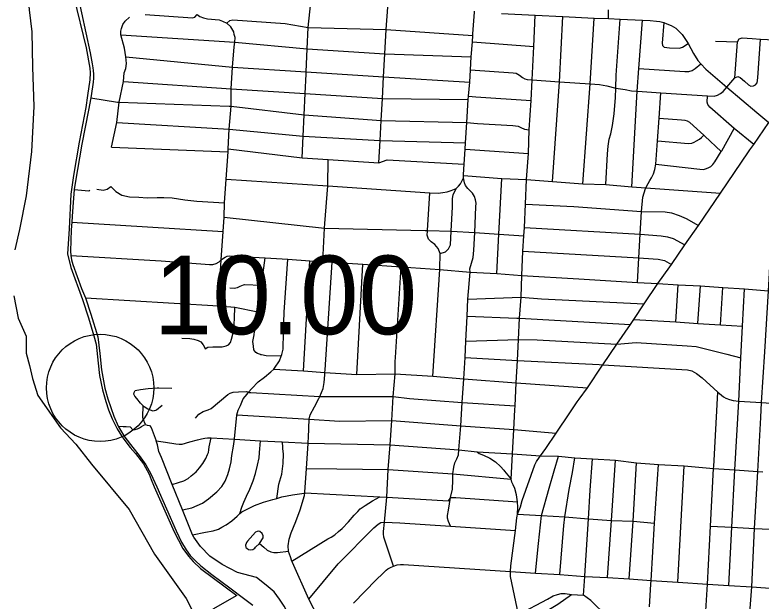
# Model space of a CAD drawing. Extents: x 1729596 to 1934326, y 644115 to 911751.
# Drawn here: x 1801847 to 1812277, y 731420 to 739620 of the extents above; entities that cross this region are included whole.
import ezdxf

# ---------------------------------------------------------------- set-up
doc = ezdxf.new("R2010")
doc.units = 0
for name, color, linetype in [('Default', 7, 'Continuous'), ('GM_X_City_Street', 7, 'Continuous'), ('GM_X_Corporation', 7, 'Continuous'), ('GM_X_Township', 7, 'Continuous'), ('GM_X_US_Route', 7, 'Continuous')]:
    doc.layers.add(name, color=color, linetype=linetype)

msp = doc.modelspace()

# ---------------------------------------------------------------- linework, layer by layer
at = {"layer": 'Default'}
msp.add_circle((1803038, 734403), 750, dxfattribs=at)
at = {"layer": 'GM_X_City_Street'}
for points in [[(1805917, 738818), (1805917, 738825), (1805932, 739144), (1805946, 739442), (1805982, 739794)], [(1806936, 737550), (1806953, 737863), (1806968, 738144), (1806985, 738451), (1807001, 738756), (1807018, 739077), (1807035, 739414), (1807059, 739728)], [(1810142, 739569), (1810142, 739692)], [(1803196, 737770), (1803273, 738114), (1803303, 738398), (1803363, 738691), (1803373, 738808), (1803396, 738870), (1803405, 738941), (1803398, 739035), (1803381, 739154), (1803329, 739340), (1803329, 739395), (1803335, 739430), (1803354, 739485), (1803387, 739533), (1803448, 739591)], [(1803669, 739626), (1804328, 739580), (1804361, 739591), (1804394, 739625), (1804434, 739597), (1804481, 739578), (1804540, 739566), (1804701, 739552), (1804751, 739534), (1804809, 739505), (1804849, 739541), (1804892, 739552), (1805623, 739499), (1805946, 739442), (1807035, 739414), (1808248, 739330)], [(1808250, 739355), (1808272, 739661), (1808272, 739674)], [(1808647, 739638), (1809119, 739616), (1809505, 739596), (1809946, 739574), (1810142, 739569), (1810308, 739562), (1810618, 739545), (1810728, 739540), (1810813, 739533), (1810862, 739527), (1810916, 739514), (1810962, 739497), (1811018, 739471), (1811084, 739433), (1811138, 739385), (1811174, 739345), (1811257, 739222), (1811333, 739081), (1811395, 738983), (1811435, 738935), (1811507, 738862), (1811798, 738609), (1812216, 738255), (1812384, 738116)], [(1808836, 734094), (1808839, 734150), (1808853, 734473), (1808872, 734786), (1808886, 735079), (1808902, 735376), (1808922, 735673), (1808931, 735977), (1808949, 736314), (1808962, 736531), (1808969, 736648), (1808986, 736972), (1808999, 737316), (1809026, 737680), (1809037, 738014), (1809064, 738421), (1809077, 738710), (1809099, 739180), (1809119, 739616)], [(1809360, 737289), (1809461, 738686), (1809505, 739596)], [(1804914, 739175), (1804920, 739241), (1804927, 739306), (1804914, 739346), (1804905, 739384), (1804864, 739452), (1804809, 739505)], [(1809787, 737259), (1809888, 738656), (1809946, 739574)], [(1810107, 737246), (1810128, 737678), (1810139, 737783), (1810153, 737881), (1810175, 737958), (1810200, 738074), (1810222, 738237), (1810240, 738467), (1810248, 738597), (1810252, 738778), (1810308, 739562)], [(1810471, 737213), (1810547, 738553), (1810569, 738870), (1810618, 739545)], [(1810916, 739514), (1810894, 739226), (1810898, 739193), (1810923, 739170), (1810999, 739161), (1811136, 739155), (1811178, 739168), (1811257, 739222)], [(1803329, 739340), (1804920, 739241), (1805932, 739144), (1807018, 739077), (1808225, 739036)], [(1808119, 737386), (1808128, 737531), (1808143, 737743), (1808144, 737832), (1808166, 738116), (1808185, 738436), (1808188, 738483), (1808207, 738680), (1808215, 738854), (1808225, 739036), (1808243, 739244), (1808248, 739330), (1808250, 739355)], [(1811639, 739254), (1811948, 739245), (1811973, 739285), (1812011, 739300), (1812154, 739292), (1812270, 739283), (1812465, 739271), (1812521, 739249), (1812562, 739224), (1812675, 739086)], [(1811910, 738741), (1811952, 738759), (1811986, 738747), (1812047, 738692), (1812102, 738644), (1812136, 738625), (1812172, 738627), (1812201, 738642), (1812223, 738671), (1812230, 738739), (1812270, 739283)], [(1804691, 735551), (1804731, 736194), (1804757, 736590), (1804770, 736789), (1804778, 736991), (1804798, 737324), (1804828, 737705), (1804828, 737745), (1804844, 738022), (1804868, 738342), (1804870, 738588), (1804889, 738889), (1804914, 739175)], [(1808243, 739244), (1809099, 739180)], [(1811798, 738609), (1811910, 738741), (1811948, 739245)], [(1803398, 739035), (1804889, 738889), (1805917, 738825), (1807001, 738756), (1808207, 738680)], [(1810569, 738870), (1811209, 738830), (1811265, 738828), (1811315, 738844), (1811357, 738870), (1811435, 738935)], [(1805861, 737623), (1805875, 737923), (1805889, 738223), (1805903, 738522), (1805916, 738792), (1805917, 738818)], [(1808215, 738854), (1808812, 738810), (1808853, 738805), (1808901, 738777), (1808944, 738745), (1808973, 738728), (1809006, 738717), (1809077, 738710), (1809461, 738686), (1809888, 738656), (1810017, 738645), (1810120, 738630), (1810248, 738597), (1810378, 738576), (1810466, 738557), (1810547, 738553), (1810551, 738553)], [(1803363, 738691), (1804870, 738588), (1805903, 738522), (1806985, 738451), (1808185, 738436)], [(1810551, 738553), (1810876, 738530), (1811529, 738486), (1811623, 738485), (1811668, 738497), (1811708, 738519), (1811747, 738548), (1811798, 738609)], [(1802908, 738458), (1803281, 738402)], [(1808188, 738483), (1808288, 738476), (1809064, 738421)], [(1810661, 737192), (1810665, 737203), (1810698, 737261), (1810724, 737305), (1810747, 737341), (1810771, 737397), (1810790, 737458), (1810807, 737532), (1810829, 737857), (1810853, 738175), (1810876, 738530)], [(1812174, 737806), (1811903, 738031), (1811561, 738329), (1811534, 738365), (1811525, 738401), (1811529, 738486)], [(1803281, 738402), (1803303, 738398), (1804840, 738343)], [(1804840, 738343), (1804868, 738342), (1805889, 738223), (1806968, 738144), (1808166, 738116)], [(1810853, 738175), (1811164, 738153), (1811212, 738149), (1811246, 738140), (1811276, 738118), (1811334, 738068), (1811476, 737940), (1811491, 737926), (1811720, 737709)], [(1803273, 738114), (1804844, 738022), (1805875, 737923), (1806953, 737863), (1806959, 737863), (1808144, 737832)], [(1808166, 738116), (1808315, 738102), (1808805, 738072), (1808881, 738064), (1808919, 738045), (1808969, 738020), (1809037, 738014)], [(1810807, 737532), (1811421, 737461), (1811473, 737459), (1811502, 737466), (1811538, 737482), (1811574, 737502), (1811602, 737527), (1811629, 737567), (1811720, 737709), (1811727, 737720), (1811903, 738031)], [(1812120, 737732), (1812174, 737806), (1812384, 738116), (1812387, 738121)], [(1810829, 737857), (1811263, 737821), (1811311, 737828), (1811341, 737840), (1811376, 737859), (1811416, 737883), (1811442, 737907), (1811476, 737940)], [(1812121, 731255), (1812147, 731618), (1812186, 732437), (1812230, 733234), (1812272, 733988), (1812285, 734197), (1812328, 734907), (1812381, 735762), (1812390, 735924), (1812420, 736462), (1812451, 736956), (1812476, 737414), (1812477, 737457), (1812474, 737530), (1812463, 737630), (1812435, 737794), (1812425, 737857)], [(1803196, 737770), (1804828, 737705)], [(1804828, 737745), (1805861, 737623), (1806227, 737598), (1806936, 737550), (1807052, 737595), (1808128, 737531)], [(1808143, 737743), (1809026, 737680)], [(1811709, 737125), (1812102, 737707), (1812120, 737732)], [(1806180, 736700), (1806221, 737230), (1806227, 737598)], [(1804798, 737324), (1806221, 737230)], [(1806221, 737230), (1807649, 737132), (1807762, 737128), (1807830, 737135), (1807891, 737145), (1807944, 737162), (1808013, 737193), (1808047, 737223), (1808075, 737255), (1808117, 737339)], [(1807938, 732467), (1807908, 732535), (1807893, 732581), (1807895, 732619), (1807906, 732691), (1807937, 732869), (1807962, 732986), (1807967, 733114), (1807970, 733200), (1807981, 733295), (1807995, 733354), (1808026, 733412), (1808048, 733465), (1808051, 733537), (1808081, 733874), (1808098, 734200), (1808123, 734531), (1808141, 734826), (1808150, 735056), (1808171, 735406), (1808179, 735645), (1808209, 736022), (1808208, 736066), (1808251, 736228), (1808261, 736331), (1808278, 736575), (1808292, 736936), (1808296, 736989), (1808286, 737032), (1808271, 737080), (1808243, 737125), (1808180, 737191), (1808145, 737235), (1808130, 737272), (1808117, 737339), (1808118, 737375), (1808119, 737386)], [(1808118, 737375), (1808655, 737333), (1808999, 737316), (1809360, 737289), (1809787, 737259), (1810107, 737246), (1810471, 737213), (1810665, 737203), (1811709, 737125)], [(1808584, 736001), (1808612, 736555), (1808655, 737333)], [(1802990, 737183), (1803079, 737170), (1803137, 737183), (1803190, 737220)], [(1803190, 737220), (1803257, 737149), (1803343, 737097), (1803448, 737075), (1803580, 737069), (1803697, 737060), (1803835, 737066), (1803927, 737066), (1804047, 737060), (1804223, 737032), (1804389, 737014), (1804778, 736991)], [(1807791, 736284), (1807864, 736308), (1807907, 736348), (1807937, 736405), (1807947, 736595), (1807962, 736937), (1807966, 737052), (1807975, 737103), (1808013, 737193)], [(1810548, 735879), (1810570, 736221), (1810587, 736552), (1810606, 736869), (1810624, 737073), (1810661, 737192)], [(1802677, 737178), (1802879, 737161), (1802896, 737168)], [(1807613, 736595), (1807614, 736605), (1807649, 737132)], [(1811001, 736096), (1811024, 736129), (1811213, 736402), (1811402, 736672), (1811709, 737125)], [(1808986, 736972), (1809660, 736939), (1810606, 736869), (1810935, 736864), (1811024, 736853), (1811132, 736816), (1811230, 736772), (1811402, 736672)], [(1804770, 736789), (1806175, 736638), (1807581, 736606)], [(1802642, 736721), (1804757, 736590)], [(1806150, 736172), (1806175, 736638), (1806180, 736700)], [(1807581, 736606), (1807614, 736605), (1807947, 736595), (1808278, 736575), (1808612, 736555), (1808962, 736531)], [(1807791, 736284), (1807791, 736284), (1807764, 736351), (1807717, 736408), (1807667, 736448), (1807630, 736485), (1807610, 736541), (1807613, 736595)], [(1808969, 736648), (1810587, 736552), (1810882, 736532), (1810971, 736516), (1811049, 736494), (1811213, 736402)], [(1802630, 736256), (1803891, 736178), (1804565, 736128), (1804614, 736130), (1804662, 736143), (1804700, 736164), (1804731, 736194), (1804762, 736218), (1804785, 736232), (1804816, 736244), (1804847, 736250), (1805345, 736222), (1805662, 736202), (1805971, 736182), (1806150, 736172), (1806280, 736163), (1806708, 736134), (1807247, 736097), (1807787, 736060), (1808209, 736022), (1808584, 736001), (1808931, 735977), (1809731, 735930), (1810548, 735879), (1810835, 735862), (1811120, 735845), (1811430, 735829), (1811741, 735808), (1812043, 735789), (1812381, 735762)], [(1807787, 736069), (1807791, 736284)], [(1808949, 736314), (1810570, 736221), (1810768, 736207), (1810840, 736204), (1810926, 736187), (1811024, 736129)], [(1804188, 732696), (1804318, 732724), (1804467, 732790), (1804554, 732851), (1804671, 732949), (1804738, 733021), (1804785, 733096), (1804824, 733191), (1804847, 733269), (1804872, 733367), (1804881, 733458), (1804904, 733588), (1804917, 733684), (1804918, 733692), (1804942, 733927), (1804947, 734015), (1804950, 734027), (1804966, 734093), (1805001, 734154), (1805036, 734250), (1805093, 734317), (1805114, 734341), (1805160, 734394), (1805247, 734487), (1805334, 734554), (1805425, 734629), (1805464, 734666), (1805476, 734678), (1805545, 734779), (1805569, 734845), (1805578, 734869), (1805597, 734945), (1805603, 735178), (1805612, 735464), (1805662, 736202)], [(1805285, 734867), (1805279, 734868), (1805239, 734883), (1805215, 734899), (1805188, 734933), (1805180, 734985), (1805175, 735053), (1805190, 735143), (1805197, 735193), (1805202, 735205), (1805219, 735248), (1805228, 735312), (1805239, 735402), (1805243, 735468), (1805246, 735528), (1805257, 735575), (1805273, 735611), (1805282, 735657), (1805291, 735783), (1805295, 735841), (1805345, 736222)], [(1805880, 734639), (1805971, 736182)], [(1806182, 734654), (1806280, 736163)], [(1806625, 734590), (1806708, 736134)], [(1807167, 734828), (1807247, 736097)], [(1807689, 734567), (1807787, 736060), (1807787, 736069)], [(1810060, 734721), (1810063, 734726), (1810261, 735013), (1810450, 735291), (1810500, 735361), (1810645, 735578), (1810835, 735862), (1811001, 736096)], [(1804851, 735800), (1804913, 735799), (1804959, 735809), (1804995, 735824), (1805041, 735844), (1805044, 735846)], [(1805044, 735846), (1805044, 735846), (1805056, 735851), (1805295, 735841)], [(1811087, 735329), (1811120, 735845)], [(1811395, 735302), (1811430, 735829)], [(1811709, 735285), (1811741, 735808)], [(1811826, 731636), (1811868, 732452), (1811911, 733255), (1811966, 734219), (1811995, 734825), (1812016, 735265), (1812043, 735789)], [(1802832, 735664), (1804691, 735551), (1804923, 735530), (1805243, 735468)], [(1808179, 735645), (1808922, 735673), (1809206, 735650), (1810645, 735578)], [(1804908, 735216), (1804911, 735292), (1804916, 735376), (1804923, 735530)], [(1808171, 735406), (1808861, 735378)], [(1808861, 735378), (1808902, 735376), (1810450, 735291)], [(1810500, 735361), (1811087, 735329), (1811395, 735302), (1811709, 735285), (1812016, 735265)], [(1804614, 734975), (1804615, 734975), (1804669, 734977), (1804743, 734978), (1804800, 734989), (1804832, 735005), (1804860, 735037), (1804873, 735082), (1804892, 735152), (1804908, 735216)], [(1804908, 735216), (1805202, 735205)], [(1804182, 735098), (1804292, 735093), (1804350, 735082), (1804410, 735064), (1804448, 735045), (1804479, 735005), (1804501, 734963), (1804505, 734949), (1804545, 734970), (1804614, 734975)], [(1808150, 735056), (1808886, 735079), (1809148, 735074), (1810261, 735013), (1810531, 735037), (1811244, 734990), (1811368, 734981), (1811798, 734873), (1811995, 734825)], [(1805569, 734845), (1805361, 734853), (1805295, 734865), (1805285, 734867)], [(1807139, 731910), (1807031, 732230), (1807006, 732314), (1806998, 732361), (1807001, 732395), (1807011, 732524), (1807044, 732873), (1807065, 733262), (1807091, 733604), (1807116, 733946), (1807135, 734281), (1807160, 734601), (1807163, 734774), (1807167, 734828)], [(1808141, 734826), (1808872, 734786), (1810014, 734728)], [(1809707, 734206), (1809732, 734244), (1809849, 734403), (1810060, 734721)], [(1810014, 734728), (1810063, 734726), (1811249, 734653), (1811309, 734640), (1811375, 734603), (1811455, 734541), (1811674, 734342), (1811722, 734299), (1811752, 734278), (1811786, 734258), (1811837, 734238), (1811885, 734227), (1811966, 734219), (1812285, 734197), (1812611, 734176), (1812908, 734157), (1813305, 734127), (1813550, 734107), (1813957, 734080), (1814298, 734057), (1814552, 734038), (1814840, 734018), (1815014, 734009), (1815058, 734013)], [(1805464, 734666), (1805880, 734639), (1806180, 734620), (1806625, 734590), (1807160, 734601), (1807689, 734567), (1808123, 734531), (1808853, 734473), (1809849, 734403)], [(1805950, 733709), (1805958, 733964), (1805973, 734026), (1806033, 734137), (1806094, 734254), (1806107, 734284), (1806154, 734395), (1806171, 734477), (1806178, 734585), (1806180, 734620), (1806182, 734654)], [(1803905, 734156), (1803826, 734091), (1803778, 734076), (1803704, 734107), (1803656, 734137), (1803641, 734152), (1803603, 734188), (1803549, 734252), (1803523, 734286), (1803508, 734313), (1803512, 734338), (1803530, 734364), (1803601, 734379), (1803709, 734394), (1803834, 734402)], [(1803834, 734402), (1803834, 734402), (1803861, 734403), (1804042, 734399)], [(1804372, 733979), (1804418, 734035), (1804479, 734074), (1804549, 734097), (1804588, 734115), (1804822, 734308), (1804858, 734328), (1804897, 734345), (1804971, 734348), (1805085, 734351), (1805114, 734341), (1805123, 734337), (1805144, 734336), (1805144, 734336)], [(1805144, 734336), (1806107, 734284), (1806110, 734284), (1807135, 734281), (1807363, 734253), (1808098, 734200), (1808839, 734150)], [(1811615, 733301), (1811674, 734342)], [(1809179, 733432), (1809194, 733454), (1809267, 733557), (1809412, 733768), (1809604, 734052), (1809707, 734206)], [(1803673, 733889), (1803638, 733964), (1803635, 733998), (1803641, 734152)], [(1808810, 733047), (1808794, 733084), (1808782, 733125), (1808804, 733479), (1808822, 733821), (1808836, 734094)], [(1804950, 734027), (1805958, 733964), (1806384, 733939), (1806384, 733939)], [(1803288, 733867), (1803360, 733863), (1803404, 733861), (1803459, 733860), (1803494, 733817), (1803528, 733821), (1803561, 733829), (1803587, 733846), (1803617, 733864), (1803649, 733882), (1803673, 733889), (1803695, 733883), (1803727, 733875), (1803751, 733850), (1803778, 733776), (1803823, 733664), (1803951, 733641), (1804095, 733621), (1804141, 733616), (1804187, 733614), (1804294, 733647), (1804398, 733674), (1804455, 733689), (1804503, 733700), (1804537, 733706), (1804583, 733703), (1804589, 733702), (1804917, 733684), (1805278, 733664), (1805582, 733648), (1805943, 733628), (1805947, 733627), (1807091, 733604), (1808051, 733537), (1808310, 733509), (1808338, 733486), (1808395, 733462), (1808484, 733420), (1808564, 733369), (1808634, 733305), (1808683, 733250)], [(1806384, 733939), (1807116, 733946), (1808081, 733874), (1808822, 733821), (1809412, 733768)], [(1806089, 731187), (1805983, 731144), (1805894, 731117), (1805818, 731106), (1805752, 731116), (1805706, 731162), (1805682, 731213), (1805613, 731348), (1805545, 731445), (1805470, 731548), (1805360, 731645), (1805225, 731749), (1804957, 731818), (1804744, 731930), (1804573, 732048), (1804440, 732185), (1804347, 732312), (1804331, 732348), (1804188, 732696), (1804046, 733050), (1803895, 733427), (1803860, 733514), (1803839, 733606), (1803823, 733664)], [(1804046, 733050), (1804133, 733077), (1804210, 733104), (1804270, 733134), (1804313, 733171), (1804379, 733226), (1804428, 733282), (1804475, 733345), (1804514, 733413), (1804540, 733470), (1804551, 733500), (1804559, 733536), (1804564, 733580), (1804589, 733702)], [(1805267, 733496), (1805267, 733497), (1805271, 733552), (1805278, 733664)], [(1805508, 732857), (1805538, 733054), (1805577, 733195), (1805597, 733343), (1805601, 733482), (1805593, 733552), (1805594, 733596), (1805582, 733648)], [(1806181, 730993), (1806089, 731187), (1805956, 731446), (1805726, 731959), (1805719, 731978), (1805699, 732037), (1805670, 732113), (1805670, 732117), (1805665, 732193), (1805680, 732287), (1805707, 732373), (1805773, 732532), (1805833, 732699), (1805895, 732898), (1805900, 732934), (1805901, 732942), (1805923, 733275), (1805947, 733624), (1805947, 733627), (1805948, 733644), (1805950, 733709)], [(1804991, 732646), (1805021, 732734), (1805048, 732805), (1805085, 732889), (1805132, 732988), (1805176, 733104), (1805211, 733207), (1805240, 733323), (1805261, 733426), (1805267, 733496)], [(1808310, 733509), (1808804, 733479), (1809194, 733454), (1809444, 733447), (1809676, 733426), (1809921, 733412), (1810242, 733390), (1810534, 733355), (1810842, 733332), (1811200, 733312), (1811614, 733277), (1811911, 733255), (1812230, 733234), (1812301, 733229)], [(1808869, 732608), (1808873, 732635), (1808914, 732738), (1808936, 732826), (1809113, 733327), (1809139, 733374), (1809179, 733432)], [(1809123, 731812), (1809166, 732227), (1809210, 732616), (1809316, 732999), (1809387, 733244), (1809444, 733447)], [(1809463, 731792), (1809521, 732477), (1809533, 732598), (1809596, 732979), (1809639, 733220), (1809676, 733426)], [(1809814, 731773), (1809867, 732572), (1809887, 732972), (1809921, 733412)], [(1810132, 731748), (1810188, 732549), (1810242, 733390)], [(1810433, 731730), (1810491, 732538), (1810534, 733355)], [(1810737, 731659), (1810740, 731707), (1810786, 732511), (1810842, 733332)], [(1805923, 733275), (1806348, 733270)], [(1806348, 733270), (1807065, 733262), (1807970, 733200), (1808782, 733125)], [(1808683, 733250), (1808692, 733239), (1808782, 733125)], [(1811112, 731685), (1811200, 733312)], [(1812065, 729436), (1811901, 729654), (1811708, 729901), (1811521, 730157), (1811483, 730224), (1811456, 730293), (1811450, 730348), (1811448, 730407), (1811451, 730493), (1811464, 730634), (1811478, 730967), (1811504, 731286), (1811526, 731655), (1811571, 732470), (1811614, 733277), (1811615, 733301)], [(1808873, 732635), (1808878, 732734), (1808872, 732807), (1808857, 732908), (1808833, 732997), (1808810, 733047)], [(1804331, 732348), (1804510, 732382), (1804617, 732405), (1804695, 732428), (1804738, 732453), (1804800, 732487), (1804877, 732542), (1804952, 732609), (1804991, 732646), (1805017, 732670), (1805194, 732756), (1805321, 732806), (1805451, 732841), (1805508, 732857), (1805578, 732877), (1805727, 732906), (1805888, 732932)], [(1805888, 732932), (1805900, 732934), (1806946, 732878), (1807044, 732873), (1807045, 732873), (1807908, 732824), (1807929, 732857)], [(1805719, 731978), (1806219, 732291), (1806269, 732316), (1806318, 732346), (1806370, 732393), (1806423, 732437), (1806508, 732528), (1806587, 732621), (1806640, 732672), (1806674, 732711), (1806743, 732757), (1806846, 732821), (1806946, 732878)], [(1807929, 732857), (1807937, 732869), (1808012, 732869), (1808872, 732807)], [(1808773, 731833), (1808780, 731911), (1808842, 732407), (1808865, 732584), (1808869, 732608)], [(1808873, 732635), (1809210, 732616), (1809533, 732598), (1809867, 732572), (1810188, 732549), (1810491, 732538), (1810786, 732511)], [(1805956, 731446), (1806366, 731941), (1806862, 732443), (1806924, 732497), (1806963, 732521), (1807011, 732524), (1807228, 732515), (1807938, 732467), (1808842, 732407)], [(1805268, 732228), (1805315, 732303), (1805317, 732333), (1805302, 732365), (1805272, 732393), (1805252, 732396), (1805234, 732394), (1805212, 732384), (1805098, 732260), (1805084, 732240), (1805078, 732224), (1805070, 732204), (1805077, 732172), (1805091, 732160), (1805111, 732144), (1805145, 732137), (1805171, 732141), (1805201, 732161), (1805210, 732174), (1805268, 732228), (1805326, 732173), (1805373, 732131), (1805423, 732108), (1805465, 732100), (1805517, 732101), (1805670, 732117)], [(1811571, 732470), (1811868, 732452), (1812186, 732437), (1812509, 732420), (1812818, 732403)], [(1806579, 731391), (1806899, 731718), (1806988, 731807), (1807035, 731852), (1807062, 731871), (1807098, 731891), (1807139, 731910), (1807190, 731925), (1807236, 731931), (1807278, 731932), (1808773, 731833), (1809123, 731812), (1809463, 731792), (1809813, 731766), (1810132, 731748), (1810433, 731730), (1810740, 731707), (1811112, 731685), (1811526, 731655), (1811826, 731636), (1812147, 731618), (1812466, 731596)], [(1808934, 730951), (1808928, 730975), (1808925, 731014), (1808915, 731064), (1808884, 731234), (1808773, 731766), (1808773, 731833)], [(1811068, 729832), (1810897, 730080), (1810721, 730340), (1810523, 730563), (1810464, 730645), (1810241, 731033), (1810175, 731126), (1810063, 731267), (1809960, 731370), (1809897, 731426), (1809797, 731501), (1809813, 731766), (1809814, 731773)], [(1810716, 731339), (1810737, 731659)], [(1808884, 731234), (1809290, 731449), (1809372, 731494), (1809432, 731512), (1809481, 731524), (1809540, 731525), (1809627, 731512), (1809797, 731501)], [(1808915, 731064), (1809144, 731200), (1809434, 731375), (1809627, 731512)]]:
    msp.add_lwpolyline(points, dxfattribs=at)
at = {"layer": 'GM_X_Corporation'}
msp.add_lwpolyline([(1802669, 739874), (1802844, 739158), (1802892, 738875), (1802901, 738809), (1802896, 738710), (1802860, 738491), (1802839, 738324), (1802746, 737839), (1802664, 737376), (1802630, 737112), (1802604, 736629), (1802584, 736279), (1802630, 736088), (1802792, 735637), (1802877, 735381), (1802950, 735133), (1802983, 735015), (1803009, 734748), (1803029, 734574), (1803069, 734376), (1803118, 734213), (1803153, 734096), (1803206, 733969), (1803274, 733830), (1803337, 733732), (1803368, 733683), (1803458, 733568), (1803531, 733484), (1803645, 733338), (1803723, 733195), (1803753, 733119), (1803795, 733020), (1804075, 732390), (1804195, 732156), (1804274, 732048), (1804339, 731973), (1804443, 731878), (1804787, 731620), (1804948, 731499), (1804614, 731308)], dxfattribs=at)
at = {"layer": 'GM_X_Township'}
for points in [[(1801652, 741717), (1801865, 740808), (1802030, 739989), (1802039, 739796), (1802044, 739693), (1802085, 739383), (1802092, 738887), (1802113, 738337), (1802079, 737710), (1802003, 737090), (1801913, 736619), (1801845, 736336)], [(1801831, 735689), (1801893, 735379), (1802003, 735125), (1802003, 734890), (1802051, 734718), (1802093, 734532), (1802168, 734298), (1802485, 733844), (1802699, 733617), (1802919, 733334), (1803442, 732701), (1803800, 732078), (1804241, 731458), (1804579, 730790), (1804820, 730439), (1805226, 729799), (1805384, 729530), (1805494, 729317), (1805543, 729124), (1805721, 728692), (1805795, 728547), (1806217, 728062)]]:
    msp.add_lwpolyline(points, dxfattribs=at)
at = {"layer": 'GM_X_US_Route'}
msp.add_lwpolyline([(1802716, 739932), (1802901, 739089), (1802928, 738935), (1802936, 738879), (1802939, 738841), (1802944, 738791), (1802944, 738735), (1802942, 738680), (1802933, 738612), (1802908, 738458), (1802875, 738289), (1802784, 737810), (1802687, 737267), (1802677, 737178), (1802657, 736937), (1802649, 736801), (1802642, 736721), (1802635, 736613), (1802622, 736315), (1802630, 736256), (1802639, 736194), (1802647, 736162), (1802657, 736127), (1802776, 735794), (1802832, 735664), (1802907, 735436), (1803006, 735116), (1803032, 734884), (1803059, 734656), (1803102, 734400), (1803147, 734250), (1803231, 734006), (1803288, 733867), (1803335, 733789), (1803384, 733715), (1803497, 733571), (1803583, 733457), (1803678, 733327), (1803748, 733198), (1803832, 733018), (1804101, 732403), (1804176, 732245), (1804240, 732137), (1804299, 732060), (1804371, 731985), (1804444, 731913), (1804600, 731790), (1804853, 731604), (1805063, 731445), (1805174, 731362)], dxfattribs=at)

# ---------------------------------------------------------------- texts
at = {"layer": 'Default'}
msp.add_text('10.00', height=1100, dxfattribs=at).set_placement((1803788, 735153))

doc.saveas('drawing.dxf')
